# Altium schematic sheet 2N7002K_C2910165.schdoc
size 127 x 101 mm
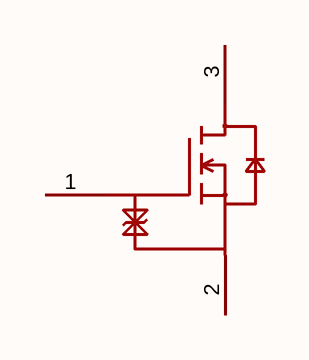
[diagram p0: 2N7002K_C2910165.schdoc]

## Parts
Q?  2n7002k_c2910165  [SOT-23-3_L2.9-W1.3-P1.90-LS2.4-BR]  (value not drawn)

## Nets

Not connected (* = marked no-connect by the designer): Q? 1(G) 2(S) 3(D)

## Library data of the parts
Q? = 2n7002k_c2910165: 数量:1个N沟道;漏源电压(Vdss):60V;连续漏极电流(Id):340mA;导通电阻(RDS(on)):3Ω@4.5V;耗散功率(Pd):350mW;阈值电压(Vgs(th)):2.5V;; Manufacturer: CJ(江苏长电/长晶); AddInBom: yes; ModelId: c62791f0466c4ae2a892c056b845b0ca; ModelName: SOT-23-3P_L2.9-W1.3-H1.0-LS2.4-P0.95; ModelTransform: 98.425,114.173,0,180,0,0,0.0005,-0.0005,0; Number: 1个N沟道; Drain to Source Voltage: 60V; Current - Continuous Drain(Id): 340mA; Pd - Power Dissipation: 350mW; Gate Threshold Voltage (Vgs(th)): 2.5V; Input Capacitance(Ciss): 40pF; Reverse Transfer Capacitance (Crss@Vds): 10pF; Type: N沟道; Output Capacitance(Coss): 30pF; Vgs: ±20V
